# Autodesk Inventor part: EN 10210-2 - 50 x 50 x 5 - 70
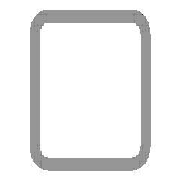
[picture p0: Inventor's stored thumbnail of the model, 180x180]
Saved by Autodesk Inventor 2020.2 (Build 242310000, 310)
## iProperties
IsCustomPart: 1
_CCFamilyMember: 16
_CCFamilyDisplayName: DIN EN 10210-2 (USAS B17.1 quadratisch) - Rohrleitung — In Klammern angegebene Größen wurden aufgehoben
_FrameMemberDoc: Frame Member File
_Version: 15.0.0
_GetPNFromCC: 1
Created: 2019-10
Part Number: EN 10210-2 - 50 x 50 x 5 - 70
Material: Stahl, weich
Description: Rohrleitung
Document SubType Name: Modeling
Standard: DIN
Designer: lutzd
Standard Revision: 2006-07
Standards Organization: DIN
Language: de-DE
Size Designation: 50 x 50 x 5
Categories: <MemberInstance><Categories><Category DisplayName="Profile" InternalName="089c4875-fa83-4c05-b084-43b9cc11f5ed" Mnemonic="GRDR"><CategoryParameter DisplayName="
Stock Number: 50 x 50 x 5
Mass: 479.81 g
Surface Area: 254.441 cm^2
Volume: 61.1222 cm^3
Density: 7.85 g/cm^3
Appearance: Semi-Polished(8)
G_L: 70,000 mm
G_W: 50,000 mm
G_H: 50,000 mm
Dimensions: 50x50x70 mm
Mass: 0,48 kg
DocNumber: ADSK-014287
Folder: .
+0FFDE9C2-6EF0-455E-9A4A-04C78E3CCDBD+SCHNITTDETAIL1: Schnittwinkel 90,00 grd
VLT_Material: Stahl, weich
Title: Profil-Bauteil
Author: lutzd
Revision Number: -
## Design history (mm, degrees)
node "Startebene"
node "Endebene"
sketch "Skizze"
  geometry: L1 (-25, -17.5)-(-25, 17.5); L2 (-17.5, 25)-(17.5, 25); L3 (25, 17.5)-(25, -17.5); L4 (17.5, -25)-(-17.5, -25); L5 (-15, 20)-(15, 20); L6 (20, 15)-(20, -15); L7 (15, -20)-(-15, -20); L8 (-20, -15)-(-20, 15); L9 (0, 37.175)-(0, -37.175) reference; L10 (-37.175, 0)-(37.175, 0) reference; A1 r 7.5 centre (-17.5, -17.5) between (-25, -17.5) and (-17.5, -25); A2 r 7.5 centre (-17.5, 17.5) between (-17.5, 25) and (-25, 17.5); A3 r 7.5 centre (17.5, 17.5) between (25, 17.5) and (17.5, 25); A4 r 7.5 centre (17.5, -17.5) between (17.5, -25) and (25, -17.5); A5 r 5 centre (-15, -15) between (-20, -15) and (-15, -20); A6 r 5 centre (-15, 15) between (-15, 20) and (-20, 15); A7 r 5 centre (15, 15) between (20, 15) and (15, 20); A8 r 5 centre (15, -15) between (15, -20) and (20, -15)
  constraints: 16 end point, 16 point on circle, 16 tangent, 8 centre point, 6 equal radius, 4 parallel, 2 perpendicular, 2 other
  dimensions: "d7" = 7.5 radius of A1 (= G_IR); "d10" = 50 distance between parallel lines of L2 L4 (= G_H); "d11" = 50 distance between parallel lines of L1 L3 (= G_W); "d12" = 5 distance between parallel lines of L3 L6 (= G_T); "d15" = 25 distance between parallel lines of L2 L10 (= 0.5 x d10); "d16" = 25 distance between parallel lines of L9 L3 (= 0.5 x d11); "d19" = 5 radius of A5 (= G_T); "d20" = 5 distance between parallel lines of L4 L7 (= G_T)
extrude "Körper" new body sketch "Skizze" stored distance "d3" = 70 (= G_L); taper "d4" = 0 deg
node "Driven Length"
  sketch "Sketch3"
    geometry: L1 (0, 0)-(10, 0) reference
    constraints: 2 end point, 1 horizontal
  workplane "Work Plane3"
  sketch "Sketch4"
    geometry: L1 (-2, 25)-(12, 25) reference; L2 (-2, 95)-(12, 95) reference
    dimensions: "d18" = 70 distance between parallel lines of L1 L2 (derived)
workplane "Arbeitsebene4"
feature "Trennen1"
body "Solid1"
other parameters: "G_W" = 50 [user parameter; used in 1 equation term], "G_H" = 50 [user parameter; used in 1 equation term], "G_T" = 5 [user parameter; used in 3 equation terms], "G_IR" = 7.5 [user parameter; used in 1 equation term], "G_L" = 70 (= d18) [user parameter; used in 1 equation term], "G_OFFSET_START" = -25 [user parameter; used in 1 equation term], "G_OFFSET_END" = 0 [user parameter; used in 1 equation term], "d13" = 25 (= -G_OFFSET_START), "d14" = 95 (= G_OFFSET_END + B_L), "B_L" = 95 [user parameter; used in 1 equation term], "d17" = 90 deg
